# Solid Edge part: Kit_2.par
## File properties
Sűrűség: 0,000 kg/m^3
Pontosság: 0,990
Author: bmolnar
Last saved by: bmolnar
Revision: 77
Username: bmolnar
Dokumentum tartalom típus: 0
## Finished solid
Body 1: solid body, 20 faces, 36 edges, 26 vertices.
  Faces by surface: cylinder 10, plane 9, cone 1
  Edges by curve: circle 22, line 14
Bounding box of the edges (mm): 85.500 x 85.350 x 6.900, from (-42.75, -40.85, 0.95) to (42.75, 44.5, 7.85).
Cylindrical faces by radius (mm): R1.5 x2, R3 x4, R31 x1, R37.5 x1, R40.85 x1, R42.75 x1
Conical faces (half-angle, radius in mm at the cone's reference point): 45 deg R30.5 x1
Planar faces by outward normal: +z 2, -z 5, oblique 2
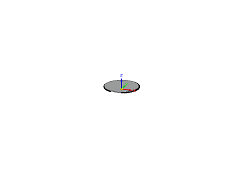
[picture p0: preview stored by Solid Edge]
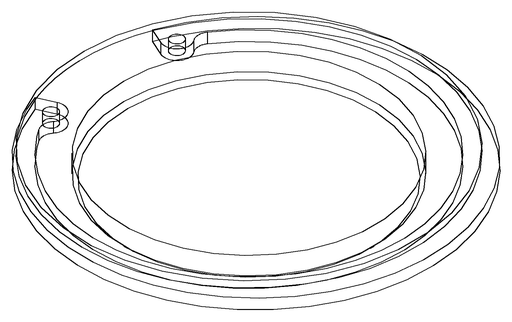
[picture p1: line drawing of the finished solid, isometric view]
